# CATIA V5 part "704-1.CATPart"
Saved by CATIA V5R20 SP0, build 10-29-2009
Part number: 704-1
Revision: TUTTO
Definition: NON CONOSCIUTO
Nomenclature: 704-1
Source: Unknown
Bounding box of the stored display mesh (mm): x -45 to 10, y -10 to 10, z 0 to 55
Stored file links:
  C:\Users\Utente\Desktop\IO LAVORO\3D X SITO CF\X SITO\704\704-1.CATPart
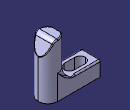
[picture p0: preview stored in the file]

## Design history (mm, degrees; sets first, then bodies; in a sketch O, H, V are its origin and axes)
Body1 "Importato1" (main body)
  Solid1: solid without history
